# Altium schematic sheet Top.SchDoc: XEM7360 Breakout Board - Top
size C; DrawnBy: Nick Kettman; Organization: Opal Kelly; Address1: 13500 SW 72nd Ave Ste 100; Address2: Portland, OR 97223; Address4: http://www.opalkelly.com/; DocumentNumber: xxx; Revision: A; SheetNumber: 1; SheetTotal: 3
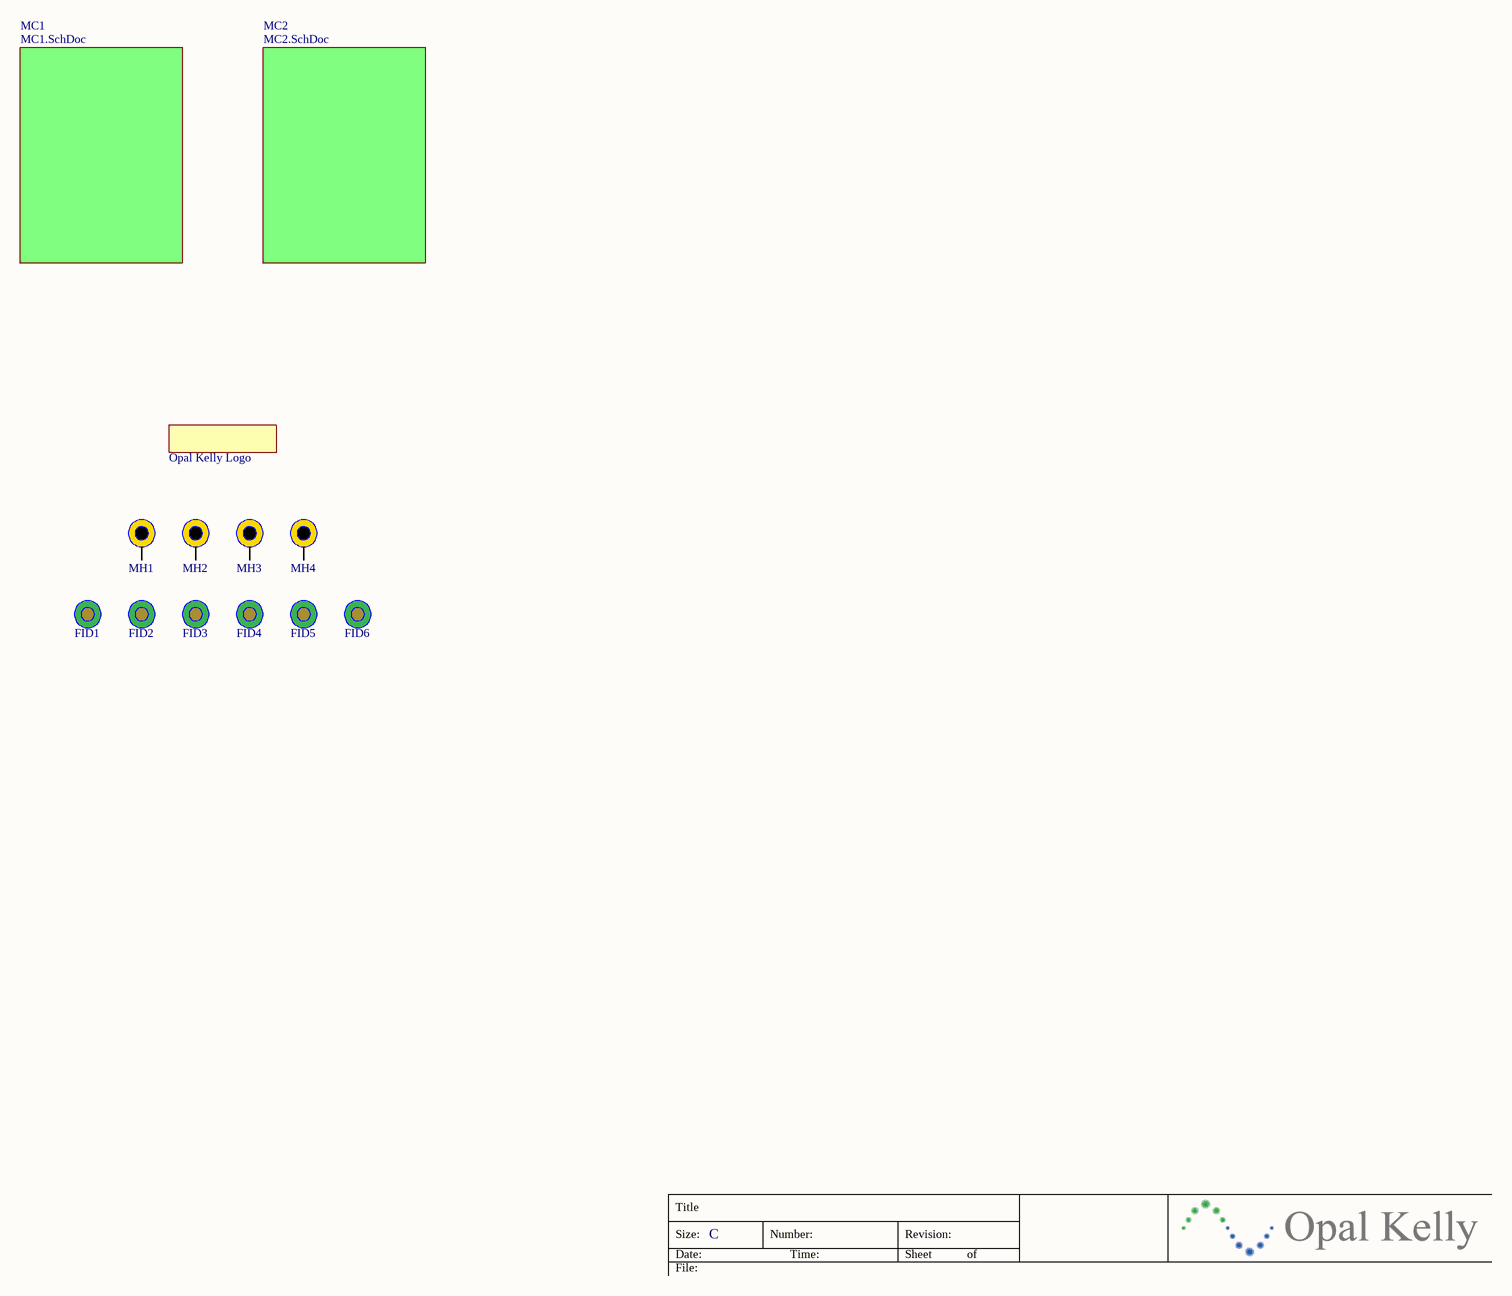
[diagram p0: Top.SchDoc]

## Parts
*1  Opal Kelly Logo  [okLogo-23x5]
FID1  FIDUCIAL  [FID1MM/2MM-SS]  (value not drawn)
FID2  FIDUCIAL  [FID1MM/2MM-SS]  (value not drawn)
FID3  FIDUCIAL  [FID1MM/2MM-SS]  (value not drawn)
FID4  FIDUCIAL  [FID1MM/2MM-SS]  (value not drawn)
FID5  FIDUCIAL  [FID1MM/2MM-SS]  (value not drawn)
FID6  FIDUCIAL  [FID1MM/2MM-SS]  (value not drawn)
MH1  MTG  [MTG-2.7/5.0-PTH]  (value not drawn)
MH2  MTG  [MTG-2.7/5.0-PTH]  (value not drawn)
MH3  MTG  [MTG-2.7/5.0-PTH]  (value not drawn)
MH4  MTG  [MTG-2.7/5.0-PTH]  (value not drawn)

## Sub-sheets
MC1 = MC1.SchDoc: no entries
MC2 = MC2.SchDoc: no entries

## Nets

Not connected (* = marked no-connect by the designer): MH1 1; MH2 1; MH3 1; MH4 1

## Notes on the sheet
- Title
- Size:
- Date:
- File:
- C
- Number:
- Time:
- Revision:
- Sheet
- of

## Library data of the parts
*1 = OKLOGO
FID1-FID6 = FIDUCIAL: PCB fiducial
MH1-MH4 = MTG: Mounting hole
